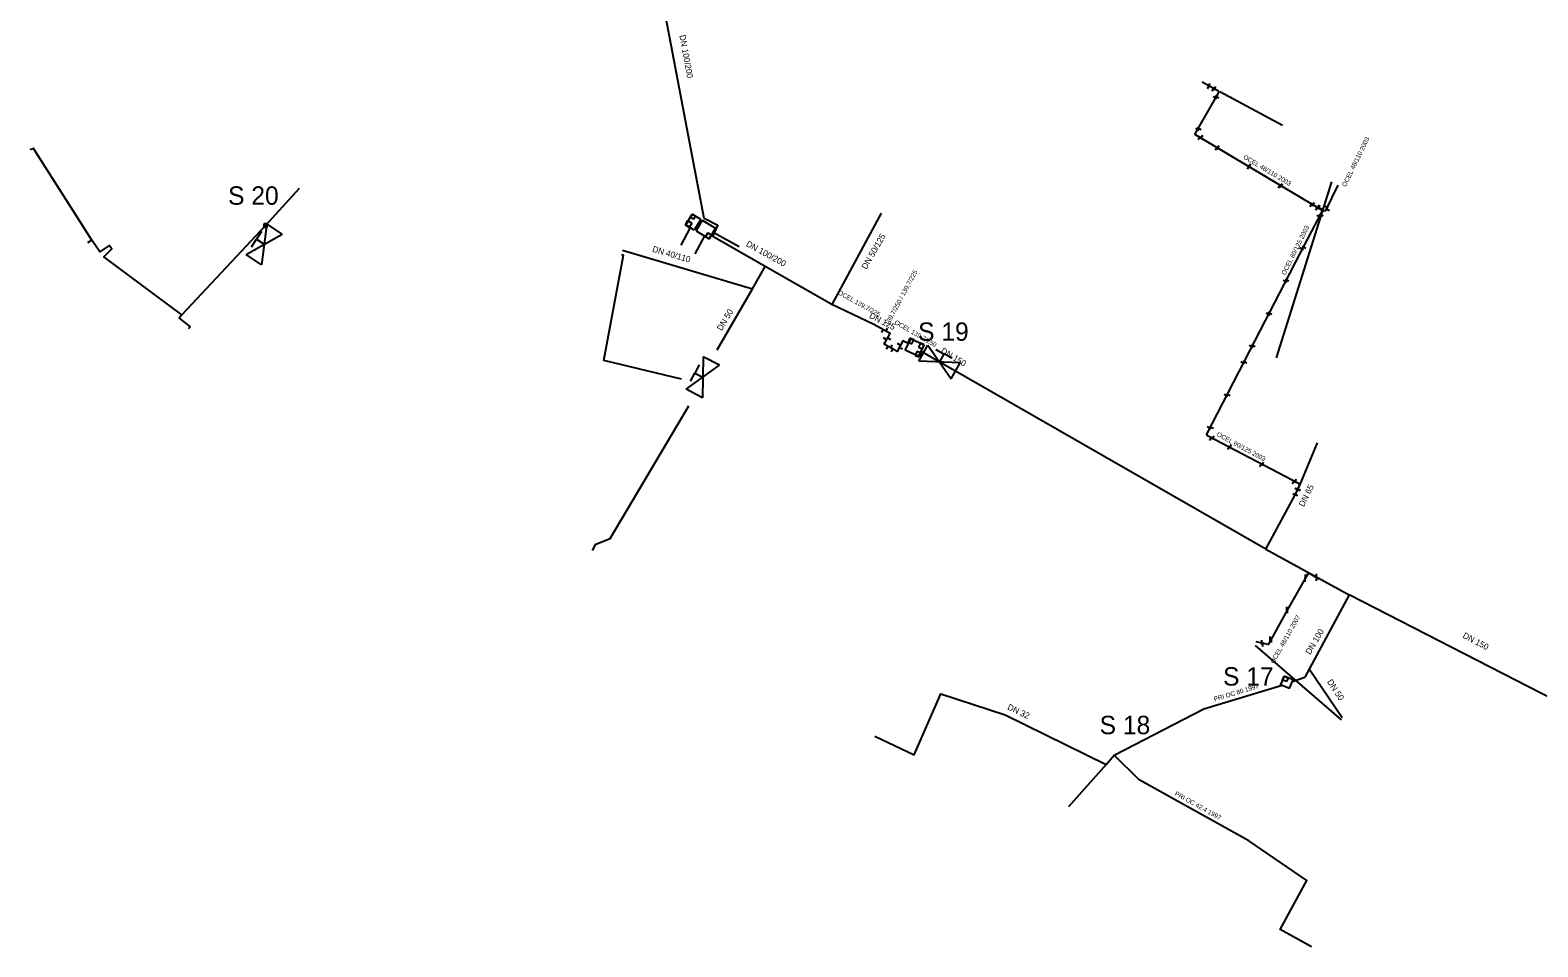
# Model space of a CAD drawing. Extents: x -642943 to -623314, y -1138561 to -1113539.
# Drawn here: x -642897.9 to -642652, y -1114479.4 to -1114329.8 of the extents above; entities that cross this region are included whole.
import ezdxf

# ---------------------------------------------------------------- set-up
doc = ezdxf.new("R2010")
doc.units = 0
for name, color, linetype in [('horkovod armatury', 7, 'Continuous'), ('horkovod dimenze', 7, 'Continuous'), ('horkovod předisol', 7, 'Continuous'), ('horkovod sváry', 7, 'Continuous'), ('horkovod trasa', 7, 'Continuous'), ('horkovod zrušený', 7, 'Continuous'), ('horkovod číslo šachty', 7, 'Continuous'), ('horkovod šachty', 7, 'Continuous')]:
    doc.layers.add(name, color=color, linetype=linetype)

# ---------------------------------------------------------------- blocks, each defined once
blk = doc.blocks.new('POINT_DISPLAY')
blk.add_line((0, 0), (0, 0))
blk = doc.blocks.new('SPH')
at = {"layer": 'horkovod sváry'}
blk.add_line((0, -0.035), (0, 0.035), dxfattribs=at)
blk = doc.blocks.new('SPH_2')
at = {"layer": 'horkovod sváry'}
blk.add_line((0, -0.035), (0, 0.035), dxfattribs=at)
blk = doc.blocks.new('SPH_1')
at = {"layer": 'horkovod sváry'}
blk.add_line((0, -0.035), (0, 0.035), dxfattribs=at)
blk = doc.blocks.new('SCH_01_82')
at = {"layer": 'horkovod armatury'}
for p, q in [((10, 5), (-10, -5)), ((-10, -5), (-10, 5)), ((-10, 5), (10, -5)), ((-5, 5), (0, 5)), ((0, 5), (0, 0)), ((5, 5), (0, 5)), ((10, -5), (10, 5))]:
    blk.add_line(p, q, dxfattribs=at)
blk = doc.blocks.new('SCH_01_83')
at = {"layer": 'horkovod armatury'}
for p, q in [((10, 5), (-10, -5)), ((-10, -5), (-10, 5)), ((-10, 5), (10, -5)), ((-5, 5), (0, 5)), ((0, 5), (0, 0)), ((5, 5), (0, 5)), ((10, -5), (10, 5))]:
    blk.add_line(p, q, dxfattribs=at)
blk = doc.blocks.new('SCH_01_84')
at = {"layer": 'horkovod armatury'}
for p, q in [((10, 5), (-10, -5)), ((-10, -5), (-10, 5)), ((-10, 5), (10, -5)), ((-5, 5), (0, 5)), ((0, 5), (0, 0)), ((5, 5), (0, 5)), ((10, -5), (10, 5))]:
    blk.add_line(p, q, dxfattribs=at)

msp = doc.modelspace()

# ---------------------------------------------------------------- linework, layer by layer
at = {"layer": 'horkovod předisol'}
for p, q in [((-642788.02, -1114360.57), (-642795, -1114323.77)), ((-642759.12, -1114359.67), (-642767.2, -1114374.6)), ((-642801.33, -1114365.7), (-642780.13, -1114372.02)), ((-642780.13, -1114372.02), (-642778.04, -1114368.39)), ((-642767.2, -1114374.6), (-642778.04, -1114368.39)), ((-642785.89, -1114381.97), (-642780.13, -1114372.02)), ((-642696.39, -1114414.52), (-642752.63, -1114382.23)), ((-642696.39, -1114414.52), (-642682.8, -1114421.95)), ((-642692.05, -1114436.07), (-642690.07, -1114435.36)), ((-642722.44, -1114449.61), (-642721.16, -1114448.13)), ((-642722.44, -1114449.61), (-642728.58, -1114456.54))]:
    msp.add_line(p, q, dxfattribs=at)
for points in [[(-642688.37, -1114358.54), (-642707.86, -1114346.9), (-642707.91, -1114346.72), (-642704.08, -1114339.99), (-642704.13, -1114339.8), (-642706.8, -1114338.32)], [(-642688.37, -1114358.54), (-642688.31, -1114358.62), (-642686.97, -1114359.31), (-642686.6, -1114359.27), (-642684.58, -1114355.14)], [(-642691.36, -1114405.16), (-642691.36, -1114405.08), (-642690.93, -1114404.09), (-642690.98, -1114403.84), (-642705.89, -1114396.03), (-642706.02, -1114395.74), (-642696.45, -1114377.17), (-642693.36, -1114371.22), (-642690.72, -1114366.02), (-642687.19, -1114359.4), (-642687.23, -1114359.1), (-642688.37, -1114358.54)], [(-642778.04, -1114368.39), (-642786.61, -1114363.48), (-642785.79, -1114361.71), (-642788.02, -1114360.57)], [(-642754.75, -1114380.93), (-642755.59, -1114380.51), (-642756.53, -1114382.23), (-642758.65, -1114381.07), (-642757.65, -1114379.34), (-642760.35, -1114377.82), (-642767.2, -1114374.6)], [(-642696.39, -1114414.52), (-642691.29, -1114405.02), (-642690.71, -1114403.69), (-642687.98, -1114397.16)], [(-642687.77, -1114419.23), (-642687.82, -1114419.32), (-642689.47, -1114418.39), (-642689.98, -1114419.27), (-642692.92, -1114424.43), (-642695.61, -1114429.28), (-642696.04, -1114430.04), (-642696.98, -1114429.85), (-642697.97, -1114429.6)], [(-642682.8, -1114421.95), (-642690.07, -1114435.36)], [(-642617.48, -1114459.73), (-642621.06, -1114456.33), (-642632.68, -1114447.69), (-642682.8, -1114421.95)], [(-642689.35, -1114434.04), (-642683.98, -1114441.96)], [(-642760.15, -1114444.99), (-642753.76, -1114448.08), (-642749.38, -1114438.11), (-642738.93, -1114441.53), (-642722.44, -1114449.61)], [(-642721.16, -1114448.13), (-642706.5, -1114440.54), (-642693.73, -1114436.7)], [(-642688.97, -1114479.39), (-642694.05, -1114476.55), (-642689.73, -1114468.55), (-642699.2, -1114462.1), (-642717.06, -1114452.15), (-642721.16, -1114448.13)]]:
    msp.add_lwpolyline(points, dxfattribs=at)
at = {"layer": 'horkovod trasa'}
for p, q in [((-642788.02, -1114360.57), (-642795, -1114323.77)), ((-642854.06, -1114355.68), (-642859.54, -1114361.72)), ((-642759.12, -1114359.67), (-642767.2, -1114374.6)), ((-642859.54, -1114361.72), (-642873.19, -1114376.25)), ((-642887.86, -1114364.08), (-642888.56, -1114364.55)), ((-642801.33, -1114365.7), (-642780.13, -1114372.02)), ((-642780.13, -1114372.02), (-642778.04, -1114368.39)), ((-642767.2, -1114374.6), (-642778.04, -1114368.39)), ((-642785.89, -1114381.97), (-642780.13, -1114372.02)), ((-642696.39, -1114414.52), (-642752.63, -1114382.23)), ((-642696.39, -1114414.52), (-642682.8, -1114421.95)), ((-642692.05, -1114436.07), (-642690.07, -1114435.36)), ((-642722.44, -1114449.61), (-642721.16, -1114448.13)), ((-642722.44, -1114449.61), (-642728.58, -1114456.54))]:
    msp.add_line(p, q, dxfattribs=at)
for points in [[(-642688.37, -1114358.54), (-642707.86, -1114346.9), (-642707.91, -1114346.72), (-642704.08, -1114339.99), (-642704.13, -1114339.8), (-642706.8, -1114338.32)], [(-642887.86, -1114364.08), (-642897.38, -1114349.13), (-642897.93, -1114349.36)], [(-642688.37, -1114358.54), (-642688.31, -1114358.62), (-642686.97, -1114359.31), (-642686.6, -1114359.27), (-642684.58, -1114355.14)], [(-642691.36, -1114405.16), (-642691.36, -1114405.08), (-642690.93, -1114404.09), (-642690.98, -1114403.84), (-642705.89, -1114396.03), (-642706.02, -1114395.74), (-642696.45, -1114377.17), (-642693.36, -1114371.22), (-642690.72, -1114366.02), (-642687.19, -1114359.4), (-642687.23, -1114359.1), (-642688.37, -1114358.54)], [(-642778.04, -1114368.39), (-642786.61, -1114363.48), (-642785.79, -1114361.71), (-642788.02, -1114360.57)], [(-642873.19, -1114376.25), (-642885.93, -1114366.8), (-642884.6, -1114365.51), (-642885.04, -1114364.97), (-642886.56, -1114365.98), (-642887.86, -1114364.08)], [(-642754.75, -1114380.93), (-642755.59, -1114380.51), (-642756.53, -1114382.23), (-642758.65, -1114381.07), (-642757.65, -1114379.34), (-642760.35, -1114377.82), (-642767.2, -1114374.6)], [(-642873.19, -1114376.25), (-642873.64, -1114376.84), (-642871.83, -1114378.23), (-642872.08, -1114378.55)], [(-642806.19, -1114414.72), (-642805.67, -1114413.71), (-642803.32, -1114412.78), (-642790.53, -1114391.14)], [(-642696.39, -1114414.52), (-642691.29, -1114405.02), (-642690.71, -1114403.69), (-642687.98, -1114397.16)], [(-642687.77, -1114419.23), (-642687.82, -1114419.32), (-642689.47, -1114418.39), (-642689.98, -1114419.27), (-642692.92, -1114424.43), (-642695.61, -1114429.28), (-642696.04, -1114430.04), (-642696.98, -1114429.85), (-642697.97, -1114429.6)], [(-642682.8, -1114421.95), (-642690.07, -1114435.36)], [(-642617.48, -1114459.73), (-642621.06, -1114456.33), (-642632.68, -1114447.69), (-642682.8, -1114421.95)], [(-642689.35, -1114434.04), (-642683.98, -1114441.96)], [(-642760.15, -1114444.99), (-642753.76, -1114448.08), (-642749.38, -1114438.11), (-642738.93, -1114441.53), (-642722.44, -1114449.61)], [(-642721.16, -1114448.13), (-642706.5, -1114440.54), (-642693.73, -1114436.7)], [(-642688.97, -1114479.39), (-642694.05, -1114476.55), (-642689.73, -1114468.55), (-642699.2, -1114462.1), (-642717.06, -1114452.15), (-642721.16, -1114448.13)]]:
    msp.add_lwpolyline(points, dxfattribs=at)
at = {"layer": 'horkovod zrušený'}
for p, q in [((-642693.66, -1114345.37), (-642703.88, -1114339.89)), ((-642694.65, -1114383.3), (-642685.64, -1114354.56)), ((-642791.01, -1114361.57), (-642789.94, -1114359.86)), ((-642790.25, -1114360.37), (-642789.94, -1114359.86)), ((-642789.94, -1114359.86), (-642789.43, -1114360.18)), ((-642788.55, -1114360.73), (-642789.94, -1114359.86)), ((-642790.28, -1114362.03), (-642791.8, -1114364.88)), ((-642790.71, -1114360.9), (-642791.13, -1114361.58)), ((-642790.46, -1114362), (-642791.13, -1114361.58)), ((-642789.61, -1114362.44), (-642791.01, -1114361.57)), ((-642790.71, -1114360.9), (-642790.03, -1114361.32)), ((-642790.03, -1114361.32), (-642790.46, -1114362)), ((-642789.74, -1114360.68), (-642790.25, -1114360.37)), ((-642789.74, -1114360.68), (-642789.43, -1114360.18)), ((-642788.55, -1114360.73), (-642789.61, -1114362.44)), ((-642788.31, -1114360.84), (-642789.33, -1114362.56)), ((-642788.69, -1114361.47), (-642788.92, -1114361.32)), ((-642788.31, -1114360.84), (-642786.15, -1114362.13)), ((-642786.15, -1114362.13), (-642787.17, -1114363.85)), ((-642787.93, -1114363.4), (-642789.55, -1114366.31)), ((-642789.33, -1114362.56), (-642787.17, -1114363.85)), ((-642787.41, -1114362.89), (-642787.77, -1114363.49)), ((-642787.77, -1114363.49), (-642787.17, -1114363.85)), ((-642787.41, -1114362.89), (-642786.81, -1114363.25)), ((-642787.17, -1114363.85), (-642786.81, -1114363.25)), ((-642786.52, -1114362.76), (-642782.28, -1114365.12)), ((-642698.14, -1114430.22), (-642684.1, -1114442.35))]:
    msp.add_line(p, q, dxfattribs=at)
msp.add_lwpolyline([(-642791.7, -1114386.77), (-642804.36, -1114383.73), (-642801.18, -1114366.54), (-642801.47, -1114366.49)], dxfattribs=at)
at = {"layer": 'horkovod šachty'}
for p, q in [((-642859.8, -1114361.45), (-642859.8, -1114361.95)), ((-642859.3, -1114361.45), (-642859.8, -1114361.45)), ((-642859.8, -1114361.95), (-642859.3, -1114361.95)), ((-642859.3, -1114361.95), (-642859.3, -1114361.45)), ((-642754.46, -1114380.07), (-642754.76, -1114380.7)), ((-642754.76, -1114380.7), (-642754.13, -1114381)), ((-642753.83, -1114380.37), (-642754.46, -1114380.07)), ((-642754.13, -1114381), (-642753.83, -1114380.37)), ((-642752.75, -1114380.88), (-642753.05, -1114381.52)), ((-642753.05, -1114381.52), (-642752.41, -1114381.82)), ((-642752.11, -1114381.18), (-642752.75, -1114380.88)), ((-642752.41, -1114381.82), (-642752.11, -1114381.18)), ((-642753.31, -1114382.23), (-642753.57, -1114382.88)), ((-642753.57, -1114382.88), (-642752.92, -1114383.14)), ((-642752.66, -1114382.49), (-642753.31, -1114382.23)), ((-642752.66, -1114382.49), (-642752.92, -1114383.14)), ((-642693.69, -1114435.85), (-642693.42, -1114435.21)), ((-642693.04, -1114436.12), (-642693.69, -1114435.85)), ((-642693.42, -1114435.21), (-642692.77, -1114435.47)), ((-642692.77, -1114435.47), (-642693.04, -1114436.12))]:
    msp.add_line(p, q, dxfattribs=at)
for points in [[(-642752.15, -1114381.23), (-642754.38, -1114380.16), (-642755.24, -1114381.96), (-642753.02, -1114383.04), (-642752.15, -1114381.23)], [(-642693.42, -1114435.21), (-642693.99, -1114436.59), (-642692.52, -1114437.2), (-642691.94, -1114435.82), (-642693.42, -1114435.21)]]:
    msp.add_lwpolyline(points, dxfattribs=at)

# ---------------------------------------------------------------- block references
at = {"layer": 'horkovod armatury'}
for name, p, xscale, yscale, rotation in [('SCH_01_84', (-642859.76, -1114364.76), 0.3000065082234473, 0.3000065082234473, 56.18907109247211), ('SCH_01_82', (-642749.62, -1114383.96), 0.30002816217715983, 0.3000281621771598, -28.709109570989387), ('SCH_01_83', (-642788.21, -1114386.46), 0.2999961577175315, 0.2999961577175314, 62.357025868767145)]:
    msp.add_blockref(name, p, dxfattribs=dict(at, xscale=xscale, yscale=yscale, rotation=rotation))
at = {"layer": 'horkovod sváry'}
for name, p, xscale, yscale, rotation in [('SPH', (-642705.73, -1114339.05), 9.999992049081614, 9.999992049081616, -29.577926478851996), ('SPH', (-642705.67, -1114338.81), 9.999980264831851, 9.999980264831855, -27.7585654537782), ('SPH', (-642704.99, -1114339.47), 9.999995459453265, 9.999995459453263, -27.82396529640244), ('SPH', (-642704.72, -1114339.31), 10.00001854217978, 10.00001854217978, -29.65917041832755), ('SPH', (-642704.7, -1114340.86), 10.000001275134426, 10.000001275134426, 59.8757703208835), ('SPH', (-642704.39, -1114340.76), 10.000013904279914, 10.00001390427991, 62.102756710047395), ('SPH', (-642707.6, -1114345.99), 9.999995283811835, 9.999995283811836, -123.86381591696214), ('SPH', (-642707.28, -1114345.88), 9.99998945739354, 9.999989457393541, -118.258073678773), ('SPH', (-642707.27, -1114347.44), 10.00000616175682, 10.000006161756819, 146.84213567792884), ('SPH', (-642706.93, -1114347.3), 9.99998462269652, 9.99998462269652, 149.69725944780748), ('SPH', (-642704.45, -1114349.12), 10.000008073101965, 10.000008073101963, -30.832846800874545), ('SPH', (-642704.2, -1114348.96), 9.999992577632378, 9.999992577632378, -30.831656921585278), ('SPH', (-642699.29, -1114352.2), 10.000008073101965, 10.000008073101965, 149.1671531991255), ('SPH', (-642699.09, -1114352.01), 9.999992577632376, 9.999992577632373, 149.16834307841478), ('SPH', (-642694.16, -1114355.27), 9.999988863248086, 9.999988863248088, -30.86492204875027), ('SPH', (-642693.89, -1114355.13), 10.000001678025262, 10.00000167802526, -30.75304680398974), ('SPH', (-642689.04, -1114358.33), 9.999988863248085, 9.999988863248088, 149.13507795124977), ('SPH', (-642688.68, -1114358.23), 10.000001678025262, 10.00000167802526, 149.24695319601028), ('SPH', (-642688.08, -1114358.9), 10.000001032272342, 10.000001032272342, -28.244105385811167), ('SPH', (-642688.03, -1114358.87), 9.999997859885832, 9.99999785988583, -28.02567053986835), ('SPH', (-642687.78, -1114360.23), 10.00001616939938, 10.00001616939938, 62.59252983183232), ('SPH', (-642687.82, -1114358.65), 9.999976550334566, 9.999976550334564, -26.565051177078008), ('SPH', (-642687.74, -1114358.69), 10.000019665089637, 10.000019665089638, -26.00341017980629), ('SPH', (-642687.36, -1114360.06), 10.000015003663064, 10.000015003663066, 67.47938630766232), ('SPH', (-642686.53, -1114358.72), 9.99999663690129, 9.999996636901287, 63.04775657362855), ('SPH', (-642686.35, -1114359.14), 9.999977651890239, 9.99997765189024, 64.03179307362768), ('SPH', (-642690.6, -1114365.44), 10.000021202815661, 10.000021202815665, -116.39382895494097), ('SPH', (-642690.18, -1114365.25), 10.000020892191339, 10.00002089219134, -117.11511767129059), ('SPH', (-642693.26, -1114370.8), 10.000021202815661, 10.000021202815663, 63.60617104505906), ('SPH', (-642692.94, -1114370.64), 10.000020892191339, 10.000020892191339, 62.88488232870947), ('SPH', (-642696.03, -1114376.13), 10.000008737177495, 10.000008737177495, -117.77204801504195), ('SPH', (-642695.74, -1114376.02), 9.999993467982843, 9.999993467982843, -117.08552683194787), ('SPH', (-642758.91, -1114378.85), 10.000008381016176, 10.000008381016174, -24.025716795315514), ('SPH_2', (-642758.25, -1114378.75), 9.99998882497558, 9.999988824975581, -23.940789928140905), ('SPH', (-642758.46, -1114380.22), 9.999989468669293, 9.999989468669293, 56.21292053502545), ('SPH_2', (-642758.09, -1114381.58), 9.999978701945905, 9.999978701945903, -25.979184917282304), ('SPH_1', (-642757.88, -1114380.15), 10.000017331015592, 10.000017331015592, 56.69257994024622), ('SPH_2', (-642757.48, -1114381.46), 10.000006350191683, 10.000006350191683, -24.599846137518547), ('SPH_2', (-642757.32, -1114381.98), 9.999994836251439, 9.999994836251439, -22.943583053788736), ('SPH_1', (-642756.19, -1114381.15), 10.000002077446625, 10.000002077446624, 58.921348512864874), ('SPH_2', (-642755.95, -1114381.7), 9.9999953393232, 9.999995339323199, 58.78883647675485), ('SPH', (-642698.8, -1114381.39), 10.000000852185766, 10.000000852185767, -116.98935230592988), ('SPH', (-642698.43, -1114381.28), 9.999990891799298, 9.999990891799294, -116.8182465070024), ('SPH', (-642700.17, -1114384.08), 10.000000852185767, 10.000000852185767, 63.01064769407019), ('SPH', (-642699.8, -1114383.99), 9.999990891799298, 9.999990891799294, 63.18175349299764), ('SPH', (-642702.89, -1114389.37), 10.000014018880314, 10.000014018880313, -117.6418449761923), ('SPH', (-642702.53, -1114389.25), 9.999995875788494, 9.99999587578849, -117.16046243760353), ('SPH', (-642705.65, -1114394.64), 10.000023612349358, 10.000023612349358, -116.93959435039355), ('SPH', (-642705.28, -1114394.61), 10.000011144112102, 10.000011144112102, -115.10144981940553), ('SPH', (-642705.4, -1114396.45), 10.000014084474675, 10.000014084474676, -27.274417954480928), ('SPH', (-642705.01, -1114396.31), 9.999974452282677, 9.999974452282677, -27.294348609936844), ('SPH', (-642702.51, -1114397.94), 10.000014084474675, 10.000014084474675, 152.72558204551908), ('SPH', (-642702.2, -1114397.76), 9.999974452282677, 9.999974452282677, 152.7056513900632), ('SPH', (-642697.2, -1114400.75), 10.000017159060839, 10.000017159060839, -27.674066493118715), ('SPH', (-642696.92, -1114400.61), 9.999981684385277, 9.99998168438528, -27.457473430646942), ('SPH', (-642691.88, -1114403.54), 10.000004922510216, 10.000004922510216, -25.942314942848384), ('SPH', (-642691.57, -1114403.39), 10.000004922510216, 10.000004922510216, -25.942314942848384), ('SPH', (-642691.7, -1114405.56), 9.999983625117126, 9.999983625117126, -115.49756260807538), ('SPH', (-642691.53, -1114405.59), 9.999983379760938, 9.99998337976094, -113.96240770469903), ('SPH', (-642691.33, -1114404.71), 10.000002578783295, 10.000002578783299, 67.86441177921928), ('SPH', (-642691.28, -1114404.76), 9.999983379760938, 9.999983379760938, 66.03759229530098), ('SPH', (-642691.11, -1114404.77), 9.999982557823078, 9.99998255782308, -113.17094928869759), ('SPH', (-642691.06, -1114404.79), 10.000001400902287, 10.000001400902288, 66.38461617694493)]:
    msp.add_blockref(name, p, dxfattribs=dict(at, xscale=xscale, yscale=yscale, rotation=rotation))
at = {"layer": 'horkovod sváry', "xscale": 10, "yscale": 10}
for p in [(-642689.96, -1114419.01), (-642689.96, -1114419.01), (-642688.16, -1114418.86), (-642688.16, -1114418.86), (-642688.13, -1114419.34), (-642688.13, -1114419.34), (-642689.97, -1114419.47), (-642689.97, -1114419.47), (-642692.96, -1114424.25), (-642692.96, -1114424.25), (-642692.88, -1114424.58), (-642692.88, -1114424.58), (-642695.67, -1114429.09), (-642695.67, -1114429.09), (-642697.08, -1114429.68), (-642697.08, -1114429.68), (-642696.87, -1114430.04), (-642696.87, -1114430.04), (-642695.49, -1114429.37), (-642695.49, -1114429.37)]:
    msp.add_blockref('SPH', p, dxfattribs=at)
at = {"layer": 'horkovod zrušený'}
for p in [(-642790.58, -1114361.45), (-642789.84, -1114360.27), (-642787.29, -1114363.37)]:
    msp.add_blockref('POINT_DISPLAY', p, dxfattribs=at)
at = {"layer": 'horkovod šachty'}
for p in [(-642754.3, -1114380.54), (-642752.58, -1114381.35), (-642753.11, -1114382.68), (-642693.23, -1114435.66)]:
    msp.add_blockref('POINT_DISPLAY', p, dxfattribs=at)

# ---------------------------------------------------------------- texts
at = {"layer": 'horkovod dimenze'}
for s, height, rotation, p in [('DN 100/200', 1, 280.328, (-642792.05, -1114330.69)), ('OCEL 48/110 2003', 0.75, 63.9552, (-642683.36, -1114355.45)), ('OCEL 48/110 2003', 0.75, 329.1683, (-642700.16, -1114350.73)), ('OCEL 60/125 2003', 0.75, 63.6062, (-642693.23, -1114369.86)), ('DN 100/200', 1, 331.2428, (-642781.26, -1114365.01)), ('DN 50/125', 1, 59.9421, (-642761.55, -1114368.93)), ('DN 40/110', 1, 343.596, (-642796.54, -1114365.96)), ('139,7/250 / 139,7/225', 0.75, 61.9196, (-642757.92, -1114378.09)), ('OCEL 139,7/225', 0.75, 330.8218, (-642766.26, -1114372.87)), ('DN 50', 1, 59.398, (-642785.14, -1114378.97)), ('DN 125', 1, 332.7301, (-642761.18, -1114376.72)), ('OCEL 139,7/250', 0.75, 329.8265, (-642757.04, -1114377.71)), ('DN 150', 1, 328.605, (-642749.52, -1114382.4)), ('OCEL 60/125 2003', 0.75, 331.641, (-642704.5, -1114395.99)), ('DN 65', 1, 63.4517, (-642690.21, -1114407.67)), ('OCEL 48/110 2007', 0.75, 60.8761, (-642695.06, -1114433.26)), ('DN 100', 1, 59.8178, (-642689.15, -1114431.79)), ('DN 150', 1, 332.1505, (-642664.4, -1114428.9)), ('DN 50', 1, 303.1279, (-642686.46, -1114436.14)), ('PRI OC 80 1997', 0.75, 16.7026, (-642704.76, -1114439.35)), ('DN 32', 1, 334.6841, (-642738.65, -1114440.61)), ('PRI OC 42.4 1997', 0.75, 330.8793, (-642711.34, -1114454.61))]:
    msp.add_text(s, height=height, rotation=rotation, dxfattribs=at).set_placement(p)
at = {"layer": 'horkovod číslo šachty'}
for s, p in [('S 20', (-642865.65, -1114358.31)), ('S 19', (-642753.11, -1114380.51)), ('S 17', (-642703.38, -1114436.76)), ('S 18', (-642723.51, -1114444.69))]:
    msp.add_text(s, height=3, dxfattribs=at).set_placement(p)

doc.saveas('drawing.dxf')
